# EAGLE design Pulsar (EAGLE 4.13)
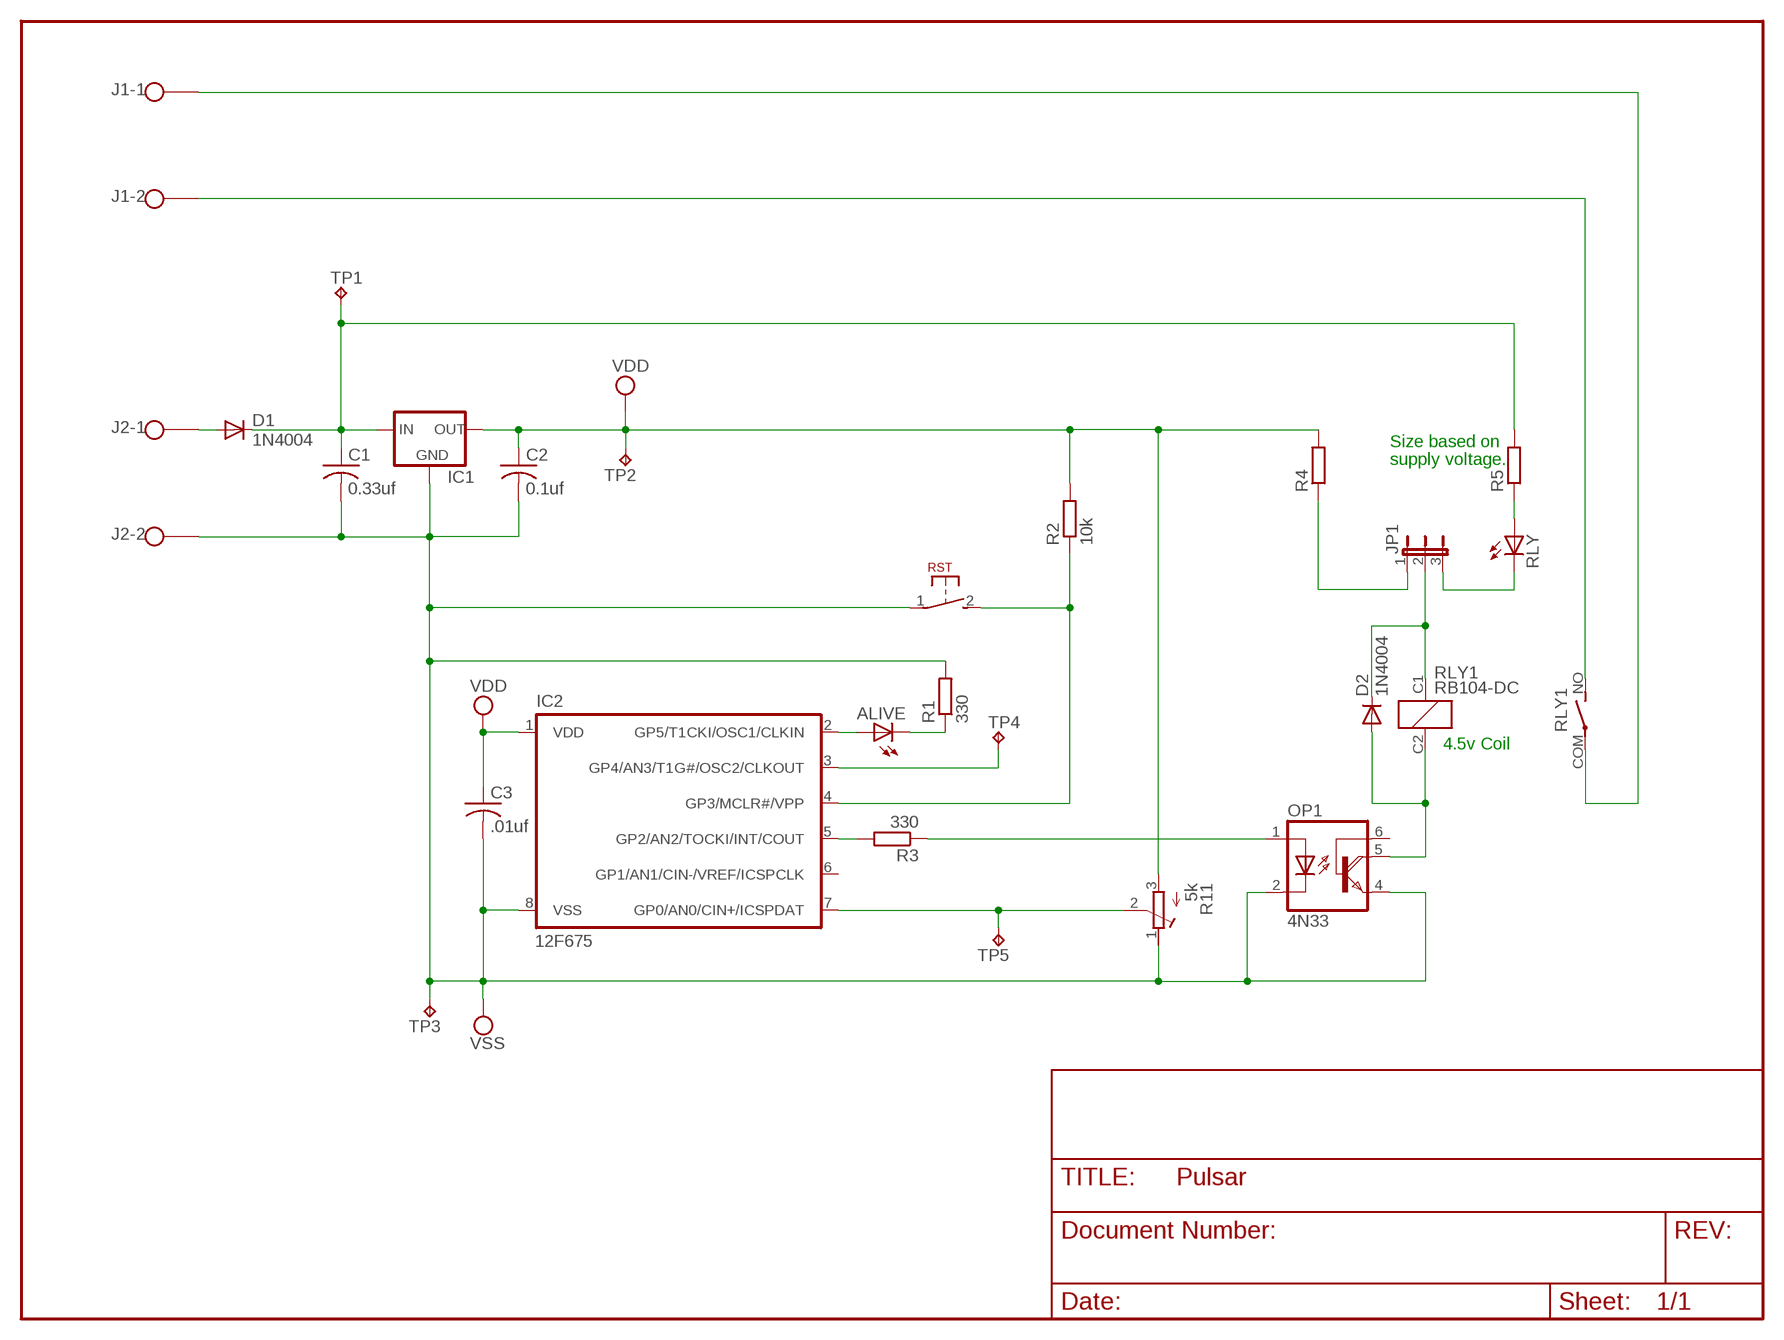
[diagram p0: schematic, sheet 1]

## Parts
ALIVE  LED5MM  [LED5MM]
C1  0.33uf  CAP-RADIAL-LEADCAP-0.20X0.20X0.125  [CAP-0.20X0.20X0.125]
C2  0.1uf  CAP-RADIAL-LEADCAP-0.20X0.20X0.125  [CAP-0.20X0.20X0.125]
C3  .01uf  CAP-RADIAL-LEADCAP-0.10X0.15X0.10  [CAP-0.10X0.15X0.10]
D1  1N4004  [DO41-10]
D2  1N4004  [DO41-10]
IC1  78XXS  [78XXS]
IC2  12F675  PIC12F675P  [DIL8]
J1  2POS  [2POL_3.5]
J2  2POS  [2POL_3.5]
JP1  JP2E  [JP2]
OP1  4N33  [DIL06]
R1  330  RES-0.25W-HORZ  [RES-0.25W-HORZ]
R2  10k  RES-0.25W-HORZ  [RES-0.25W-HORZ]
R3  330  RES-0.25W-HORZ  [RES-0.25W-HORZ]
R4  RES-0.25W-HORZ  [RES-0.25W-HORZ]
R5  RES-0.25W-HORZ  [RES-0.25W-HORZ]
R11  5k  R-TRIMMT93YB  [RTRIMT93YB]
RLY  LED5MM  [LED5MM]
RLY1  RB104-DC  [RB104]
RST  EVQ11U04M  [EVQ11]
TP1  TPPAD1-17  [P1-17]
TP2  TPPAD1-17  [P1-17]
TP3  TPPAD1-17  [P1-17]
TP4  TPPAD1-17  [P1-17]
TP5  TPPAD1-17  [P1-17]

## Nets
N$1: JP1.1 R4.1
N$2: ALIVE.A IC2.2(GP5/T1CKI/OSC1/CLKIN)
N$3 [Power]: C1.1 D1.C IC1.IN R5.2 TP1.1(TP)
N$4: ALIVE.K(C) R1.1
N$5: IC2.7(GP0/AN0/CIN+/ICSPDAT) R11.2(S) TP5.1(TP)
N$6: IC2.3(GP4/AN3/T1G#/OSC2/CLKOUT) TP4.1(TP)
N$7: JP1.3 RLY.K(C)
N$8: IC2.5(GP2/AN2/TOCKI/INT/COUT) R3.2
N$9 [Power]: D1.A J2.P$1
N$10: OP1.1(A) R3.1
N$11: D2.A OP1.5(COL) RLY1.C2
N$12: D2.C JP1.2 RLY1.C1
N$13: J1.P$2 RLY1.NO
N$14: IC2.4(GP3/MCLR#/VPP) R2.1 RST.2(S)
N$15: J1.P$1 RLY1.COM
N$16: R5.1 RLY.A
VDD [Power]: C2.1 C3.1 IC1.OUT IC2.1(VDD) R2.2 R4.2 R11.3(E) TP2.1(TP)
VSS [Power]: C1.2 C2.2 C3.2 IC1.GND IC2.8(VSS) J2.P$2 OP1.2(C) OP1.4(E) R1.2 R11.1(A) RST.1(P) TP3.1(TP)
Unconnected: IC2.6(GP1/AN1/CIN-/VREF/ICSPCLK) OP1.6(B)

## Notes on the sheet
- Size based on
- supply voltage.
- 4.5v Coil

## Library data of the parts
ALIVE RLY = led:LED: LED
C1-C3 = RCL2:CAP-RADIAL-LEAD
D1 D2 = diode:1N4004: DIODE
IC1 = v-reg:78XXS: VOLTAGE REGULATOR
IC2 = microchip:PIC12F6*: MICROCONTROLLER
J1 J2 = On-Shore Technology:2POS
JP1 = jumper:JP2E: JUMPER
OP1 = optocoupler:4N33: MOTOROLA OPTO COUPLER
R1-R5 = RCL2:RES-0.25W-HORZ
R11 = rcl:R-TRIMM: Trimm resistor
RLY1 = Fuji - Relay:RB104*
RST = Panasonic - Switch:EVQ11*
TP1-TP5 = testpad:TP

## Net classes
0 default: width 0.254 mm, drill 0.254 mm
1 Motor Current: width 2.54 mm
2 Power: width 0.508 mm, drill 0.254 mm

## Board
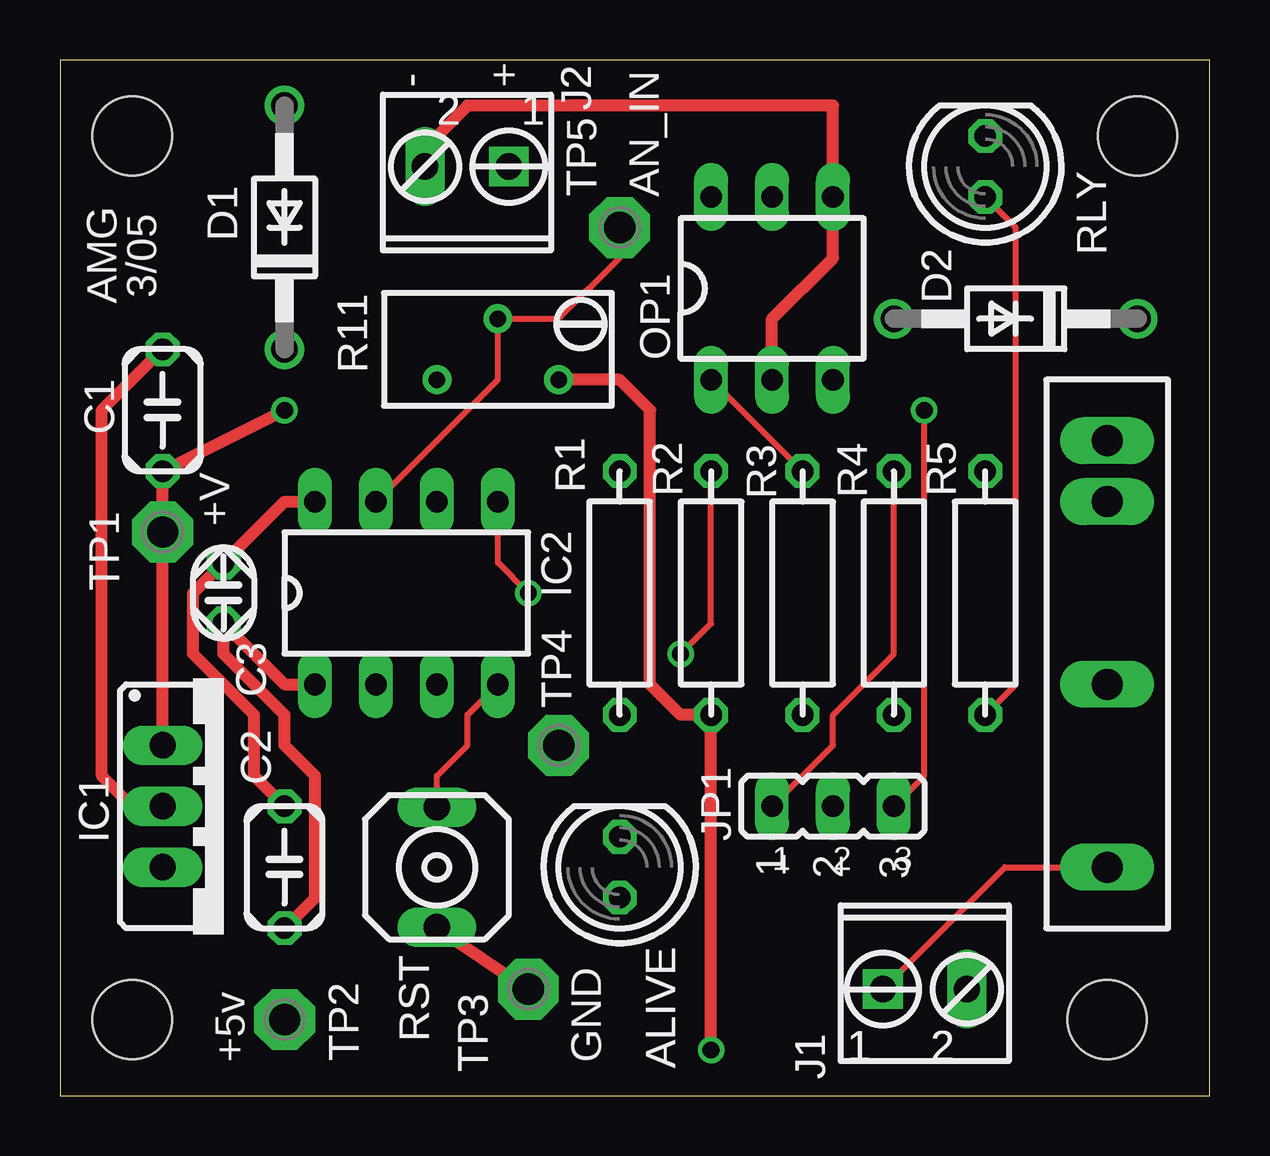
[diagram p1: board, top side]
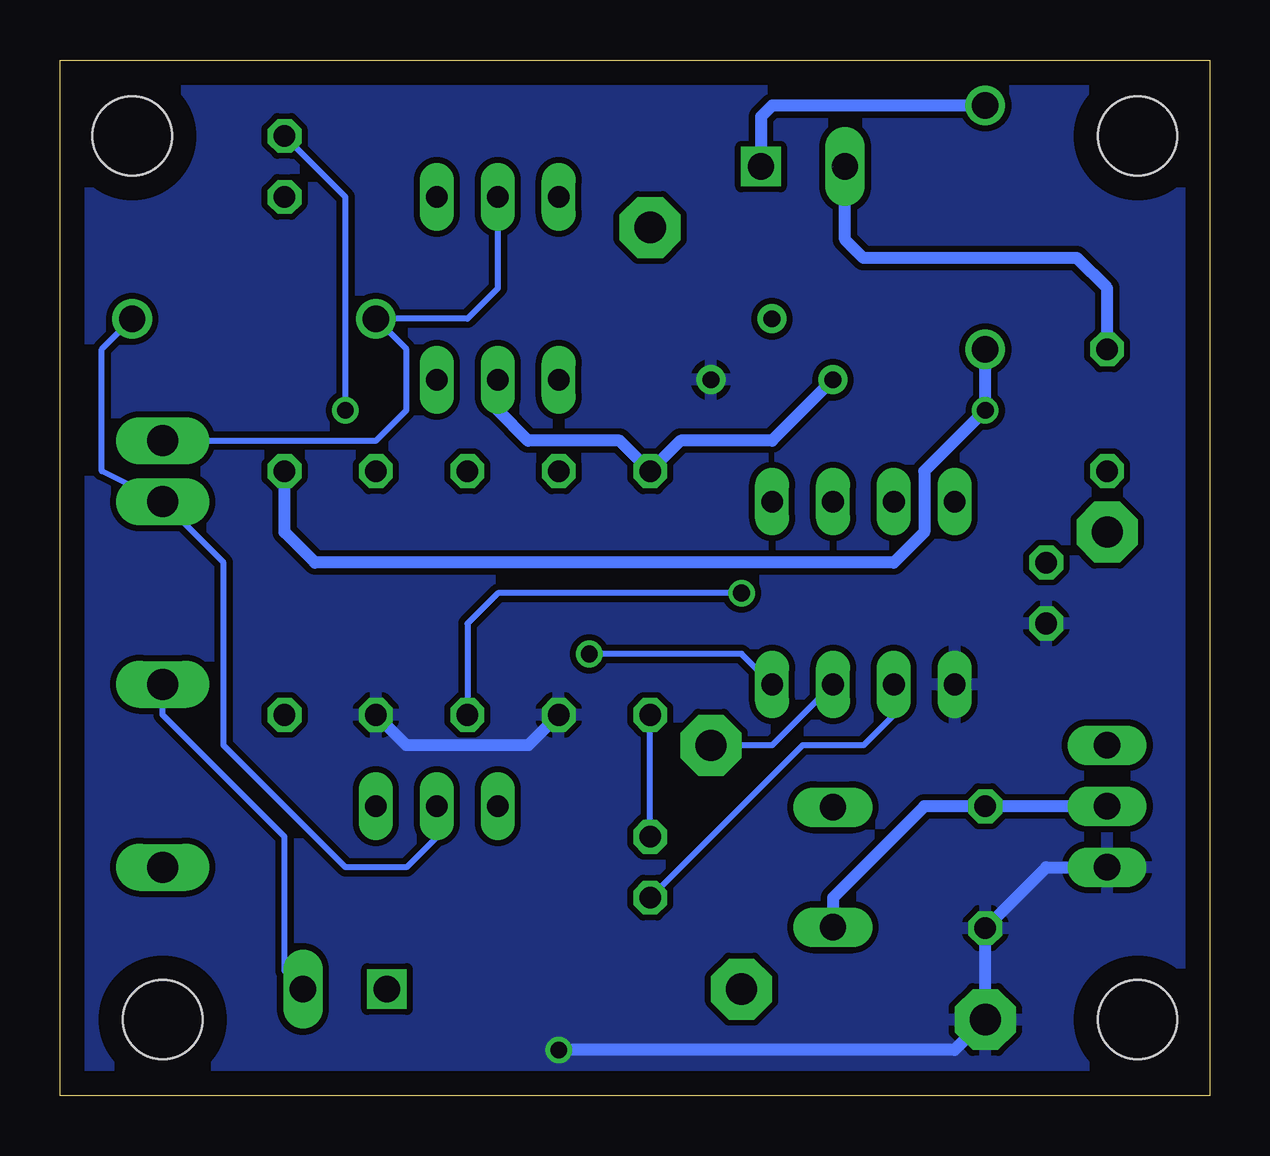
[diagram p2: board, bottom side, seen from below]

Size 47.93 x 43.17 mm. Coordinates in mm from the lower left corner, seen from the top.
Outline: 0,0 47.93,0 47.93,43.17 0,43.17 0,0
Copper layers (1*16): Top 0.035mm / dielectric 1.5mm / Bottom 0.035mm
Design rules "Olimex": minimum track width 10mil, minimum drill 24mil, track to track 10mil, track to pad 10mil, pad to pad 10mil, via to via 10mil, smd to smd 10mil, copper to edge 40mil, drill to drill 10mil, minimum pad ring 10mil, minimum via ring 8mil, stop-mask expansion 0mil, vias tented up to drill 0mil, thermal gap 10mil
Holes 3.3 mm at 3.01,40 44.92,40 43.65,3.17 3.01,3.17

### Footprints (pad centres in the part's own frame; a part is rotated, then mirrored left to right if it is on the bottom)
LED5MM = drill 0.9 octagon: A -1.27,0; K 1.27,0
CAP-0.20X0.20X0.125 = drill 0.9 octagon: 1 -2.54,0; 2 2.54,0
CAP-0.10X0.15X0.10 = drill 0.9 octagon: 1 -1.27,0; 2 1.27,0
DO41-10 = drill 1.1 round: A 5.08,0; C -5.08,0
78XXS = drill 1.1 long: GND 0,-2.54; IN -2.54,-2.54; OUT 2.54,-2.54
DIL8 = drill 0.9 long: 1 -3.81,-3.81; 2 -1.27,-3.81; 3 1.27,-3.81; 4 3.81,-3.81; 5 3.81,3.81; 6 1.27,3.81; 7 -1.27,3.81; 8 -3.81,3.81
2POL_3.5 = drill 1.1 square: P$1 -1.73,0 | drill 1.1 long: P$2 1.77,0
JP2 = drill 0.9 long: 1 -2.54,0; 2 0,0; 3 2.54,0
DIL06 = drill 0.9 long: 1 -2.54,-3.81; 2 0,-3.81; 3 2.54,-3.81; 4 2.54,3.81; 5 0,3.81; 6 -2.54,3.81
RES-0.25W-HORZ = drill 0.9 octagon: 1 -5.08,0; 2 5.08,0
RTRIMT93YB = drill 0.7 round: 1 1.27,-2.54; 2 -1.27,0; 3 1.27,2.54
RB104 = drill 1.3 long: C1 7.62,0; C2 10.16,0; COM -7.62,0; NO 0,0
EVQ11 = drill 1.1 long: 1 -2.5,0; 2 2.5,0
P1-17 = drill 1.3 pad 2.54 octagon: 1 0,0

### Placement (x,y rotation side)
ALIVE  23.33,9.52 90 top
C1  4.28,28.57 90 top
C2  9.36,9.52 90 top
C3  6.82,20.95 90 top
D1  9.36,36.19 90 top
D2  39.84,32.38 180 top
IC1  6.82,12.06 270 top
IC2  14.44,20.95 0 top
J1  36.03,4.44 0 top
J2  16.98,38.73 180 top
JP1  32.22,12.06 0 top
OP1  29.68,33.65 0 top
R1  23.33,20.95 90 top
R2  27.14,20.95 270 top
R3  30.95,20.95 270 top
R4  34.76,20.95 270 top
R5  38.57,20.95 90 top
R11  18.25,31.11 270 top
RLY  38.57,38.73 90 top
RLY1  43.65,17.14 90 top
RST  15.71,9.52 90 top
TP1  4.28,23.49 90 top
TP2  9.36,3.17 0 top
TP3  19.52,4.44 0 top
TP4  20.79,14.6 180 top
TP5  23.33,36.19 0 top

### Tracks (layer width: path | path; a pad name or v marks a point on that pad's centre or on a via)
N$1
  Top 0.254: R4.1 34.76,18.41 32.22,15.87 32.22,14.6 JP1.1
N$2
  Bottom 0.254: IC2.2 13.17,15.87 14.44,14.6 16.98,14.6 ALIVE.A
N$3  (via drill 0.7)
  Top 0.508: IC1.IN TP1.1 C1.1 v9.36,28.57
  Bottom 0.508: D1.C v9.36,28.57 11.9,26.03 11.9,23.49 13.17,22.22 37.3,22.22 38.57,23.49 R5.2
N$4
  Bottom 0.254: ALIVE.K R1.1
N$5
  Top 0.254: TP5.1 23.33,34.92 20.79,32.38 R11.2 18.25,29.84 IC2.7
N$6
  Bottom 0.254: TP4.1 18.25,14.6 IC2.3
N$7  (via drill 0.7)
  Top 0.254: JP1.3 36.03,13.33 v36.03,28.57
  Bottom 0.254: v36.03,28.57 36.03,37.46 RLY.K
N$8  (via drill 0.7)
  Top 0.254: IC2.5 18.25,22.22 v19.52,20.95
  Bottom 0.254: v19.52,20.95 29.68,20.95 30.95,19.68 R3.2
N$9
  Bottom 0.508: J2.P$1 18.71,40.81 18.25,41.27 D1.A
N$10
  Top 0.254: R3.1 OP1.1
N$11
  Bottom 0.254: OP1.5 29.68,33.65 30.95,32.38 D2.A 33.49,31.11 33.49,28.57 34.76,27.3 RLY1.C2
N$12
  Bottom 0.254: JP1.2 32.22,10.79 33.49,9.52 36.03,9.52 41.11,14.6 41.11,22.22 RLY1.C1 46.19,26.03 46.19,31.11 D2.C
N$13
  Bottom 0.254: J1.P$2 38.57,5.21 38.57,10.79 43.65,15.87 RLY1.NO
N$14  (via drill 0.7)
  Top 0.254: RST.2 15.71,13.33 16.98,14.6 16.98,15.87 IC2.4 | R2.1 27.14,19.68 v25.87,18.41
  Bottom 0.254: v25.87,18.41 19.52,18.41 IC2.4
N$15
  Top 0.254: J1.P$1 39.38,9.52 RLY1.COM
N$16
  Top 0.254: R5.1 39.84,17.14 39.84,36.19 RLY.A
VDD  (via drill 0.7)
  Top 0.508: C2.1 10.63,8.25 10.63,13.33 9.36,14.6 9.36,15.87 6.82,18.41 C3.1 9.36,17.14 IC2.1 | v27.14,1.9 R2.2 25.87,15.87 24.6,17.14 24.6,28.57 23.33,29.84 R11.3
  Bottom 0.508: IC1.OUT 6.82,9.52 C2.1 TP2.1 10.63,1.9 v27.14,1.9 | R2.2 28.41,14.6 33.49,14.6 R4.2
  pour Bottom: 0.47,31.11 0.47,0.63 47.46,0.63 47.46,42.54 0.47,42.54
VSS  (1 unrouted)
  Top 0.508: C2.2 8.09,13.33 8.09,15.87 5.55,18.41 5.55,20.95 C3.2 9.36,24.76 IC2.8 | 15.71,38.73 15.71,40 16.98,41.27 32.22,41.27 OP1.4 32.22,34.92 29.68,32.38 OP1.2 | C1.2 1.74,28.57 1.74,13.33 3.01,12.06 IC1.GND | RST.1 15.71,6.98 TP3.1
  Bottom 0.508: IC1.GND C2.2 11.9,12.06 15.71,8.25 RST.1 | OP1.2 29.68,28.57 28.41,27.3 24.6,27.3 R1.2 22.06,27.3 18.25,27.3 R11.1 | C1.2 4.28,33.65 5.55,34.92 14.44,34.92 15.21,35.69 J2.P$2 15.71,38.73

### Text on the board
Top: Text on Component Side, Signal Layer
Bottom: Text on Solder Side, Signal Layer
tNames: 2 | 2 | 2 | 1 | 1 | 1 | 1 | 1 | 1 | 2 | 2 | 2
tStop: Text on Component Side, Solder Mask Layer
bStop: Text on Solder Side, Solder Mask Layer
_tsilk: - | + | 2 | 1 | J2 | TP5 | AN_IN | D1 | D2 | RLY | AMG | 3/05 | R11 | OP1 | C1 | R2 | R3 | R4 | R1 | R5 | +V | TP1 | Text on Silkscreen Layer | IC2 | TP4 | C3 | IC1 | C2 | JP1 | 1 | 2 | 3 | RST | J1 | +5v | TP2 | TP3 | GND | ALIVE | 1 | 2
